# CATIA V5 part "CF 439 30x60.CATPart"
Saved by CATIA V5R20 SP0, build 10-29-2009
Part number: CF 439 30x60
Definition: NONE
Nomenclature: Rivoluzione1
Source: Unknown
Description: CF 439 30x60
Bounding box of the stored display mesh (mm): x -26.5 to 26.5, y 0 to 60, z -26.5 to 26.5
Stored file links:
  C:\Users\Utente\Desktop\IO LAVORO\3D X SITO CF\X SITO\CF 439\CF 439 30x60.CATPart
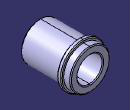
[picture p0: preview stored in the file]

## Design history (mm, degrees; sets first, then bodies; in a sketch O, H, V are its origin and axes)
Body1 "CF 439 30x60" (main body)
  Solid1: solid without history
